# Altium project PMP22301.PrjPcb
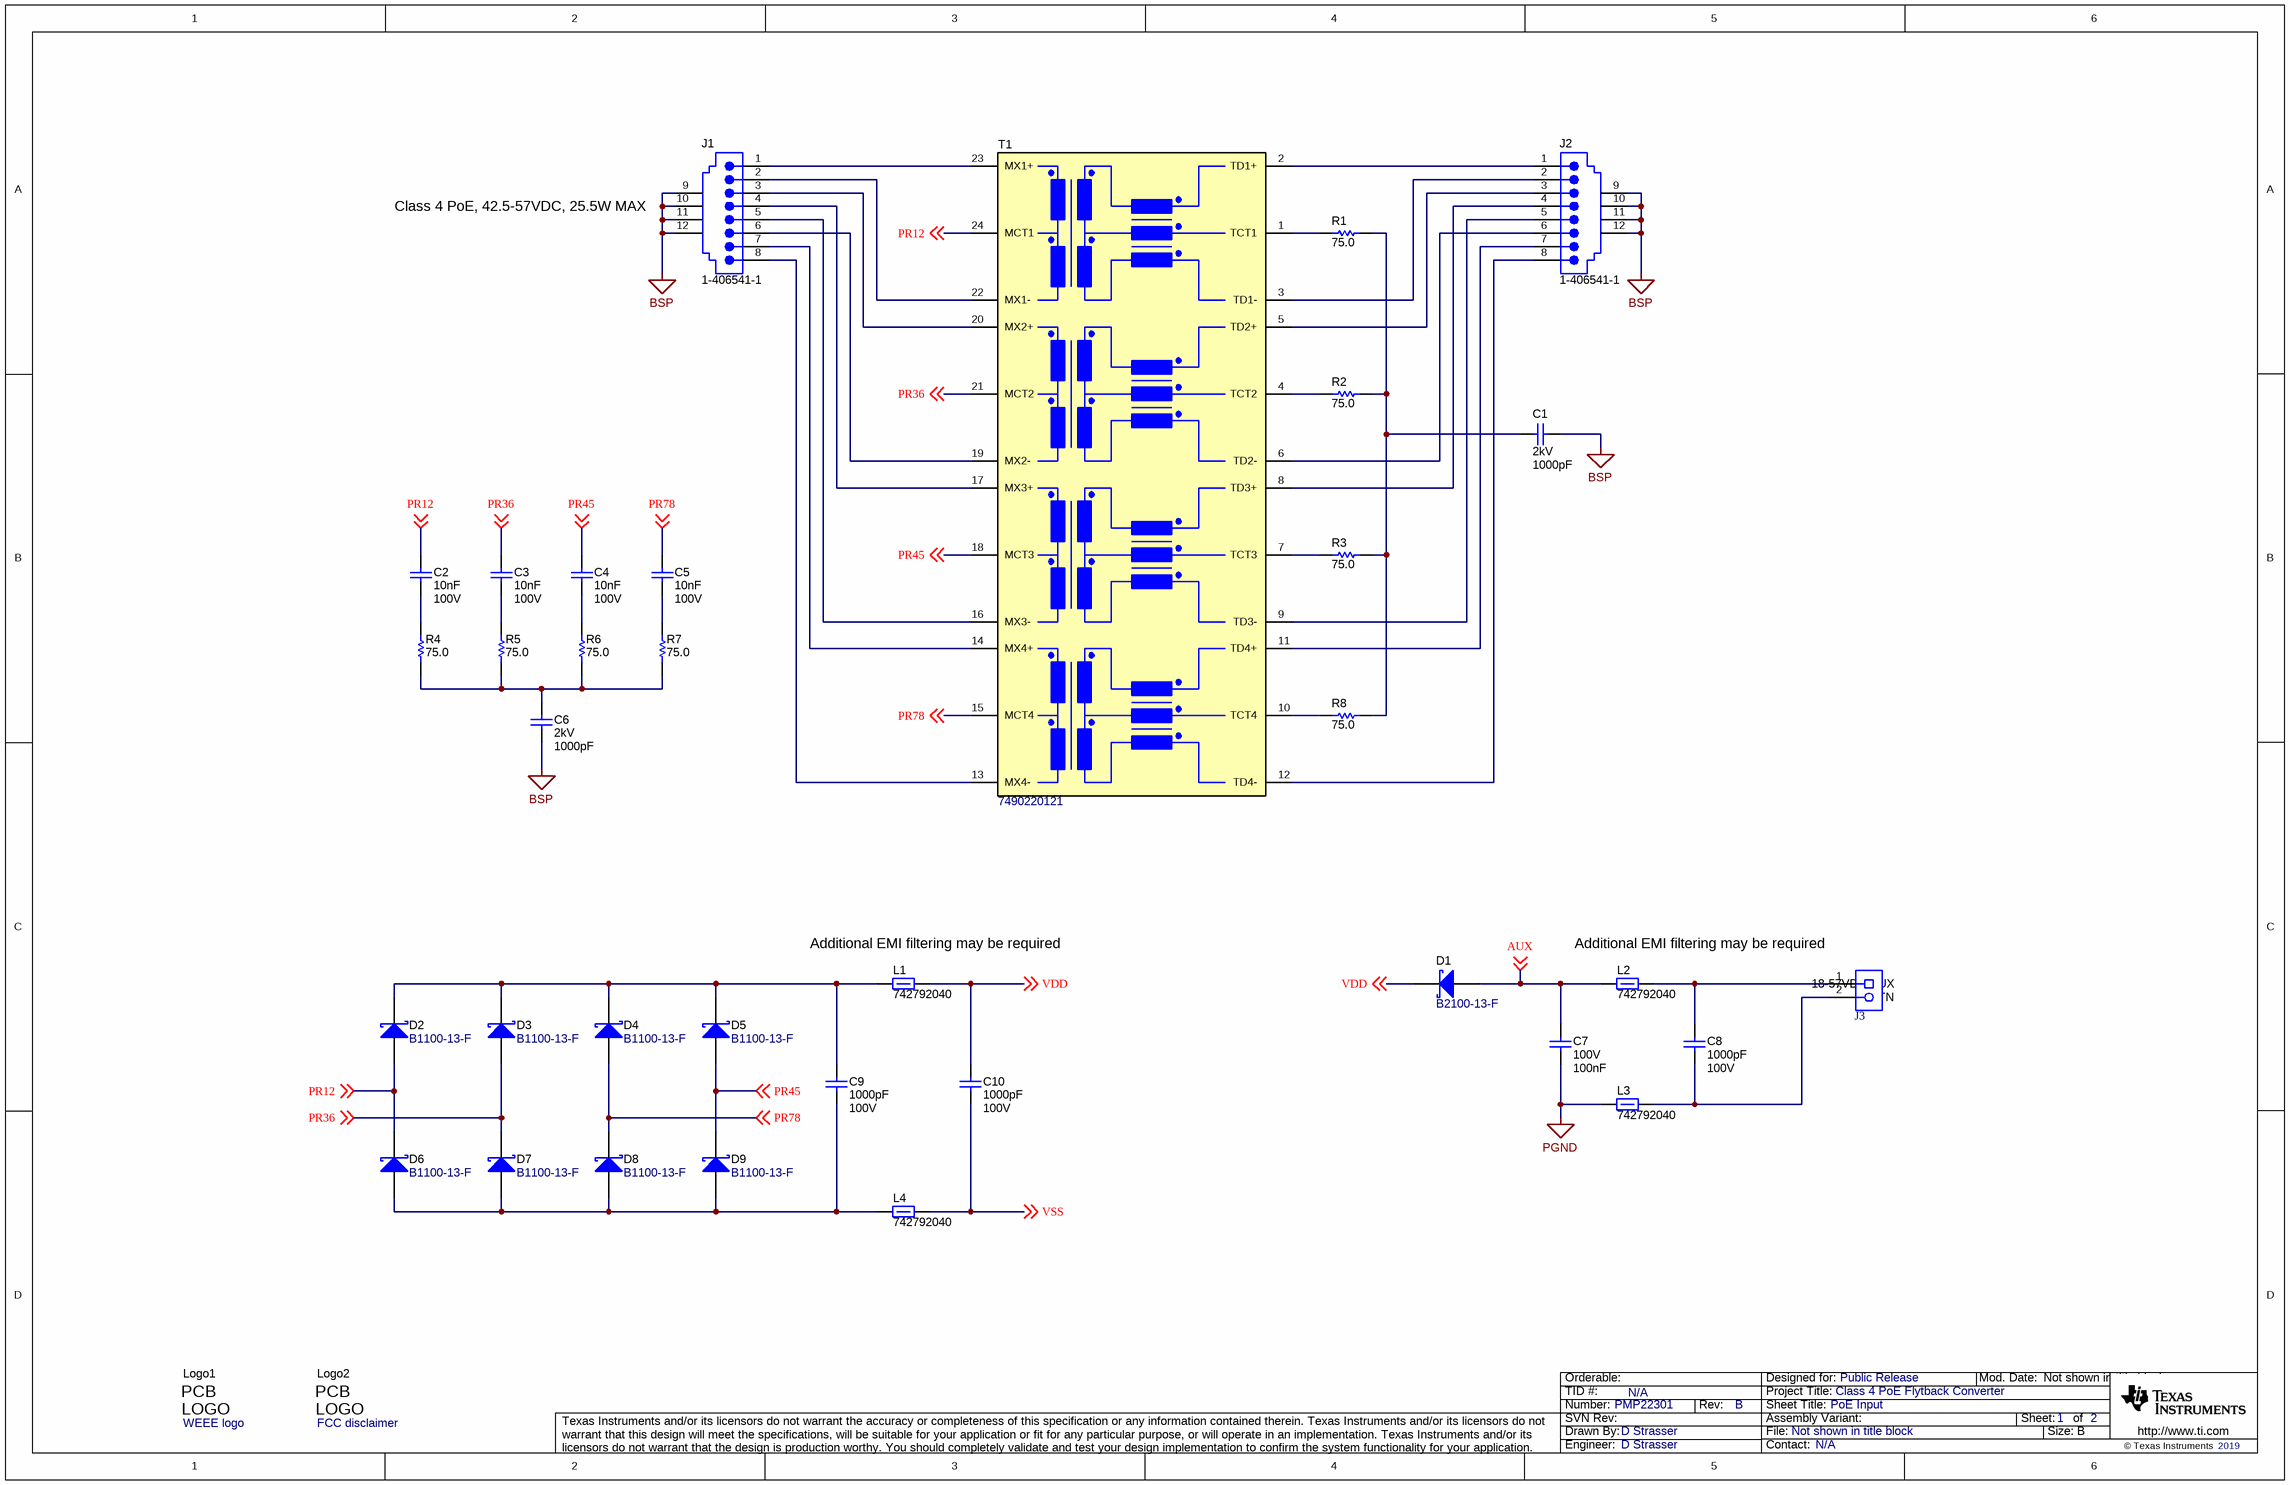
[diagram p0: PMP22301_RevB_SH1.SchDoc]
CopyrightYear: 2019; PCB_Layout: D Strasser; PCB_Rev: B; PRJ_Customer: Public Release; PRJ_Engineer: D Strasser; PRJ_Number: PMP22301; PRJ_Title: Class 4 PoE Flytback Converter; SCH_Rev: B; TechSupport: N/A; TID: N/A
2 sheets, 104 parts. Net scope: global (net labels, ports and power ports of the same name join across sheets).
Board file: PMP22301_RevB_PCB.PcbDoc
Sheets:
  PMP22301_RevB_SH1.SchDoc
  PMP22301_RevB_SH2.SchDoc

## Sheet PMP22301_RevB_SH1.SchDoc: PoE Input
size 431 x 279 mm; Date: Not shown in title block; ApprovedBy: Not shown in title block; CheckedBy: Not shown in title block; Author: Not shown in title block; CompanyName: Not shown in title block; DrawnBy: D Strasser; Engineer: Not shown in title block; Organization: Not shown in title block; Address1: Not shown in title block; Address2: Not shown in title block; Address3: Not shown in title block; Address4: Not shown in title block; DocumentNumber: 1; Revision: Use project parameter SCH_Rev; SheetNumber: 1; SheetTotal: 2; PageSetup: Record=PageOptions¦CenterHorizontal=True¦CenterVertical=True¦PrintScale=1.00¦XCorrection=1.00¦YCorrection=1.00¦PrintKind=0¦BorderSize=5000000¦LeftOffset=0¦BottomOffset=0¦Orientation=2¦PaperLength=1000¦PaperWidth=1000¦Scale=100¦PaperSource=15¦PrintQuality=600¦MediaType=1¦DitherType=10¦PaperKind=Letter¦PrintScaleMode=1

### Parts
C1  VDC_V: 2kV  ValueDisplayed: 1000pF  [1812]  (hidden comment: GR443QR73D102KW01L)
C2  Cap_F: 10nF  VDC_V: 100V  [0603L]  (hidden comment: 885012206114)
C3  Cap_F: 10nF  VDC_V: 100V  [0603L]  (hidden comment: 885012206114)
C4  Cap_F: 10nF  VDC_V: 100V  [0603L]  (hidden comment: 885012206114)
C5  Cap_F: 10nF  VDC_V: 100V  [0603L]  (hidden comment: 885012206114)
C6  VDC_V: 2kV  ValueDisplayed: 1000pF  [1812]  (hidden comment: GR443QR73D102KW01L)
C7  VDC_V: 100V  Cap_F: 100nF  [0805_HV]  (hidden comment: 885012207128)
C8  ValueDisplayed: 1000pF  Value2: 100V  [0603L]  (hidden comment: Capacitor)
C9  ValueDisplayed: 1000pF  Value2: 100V  [0603L]  (hidden comment: Capacitor)
C10  ValueDisplayed: 1000pF  Value2: 100V  [0603L]  (hidden comment: Capacitor)
D1  B2100-13-F  [SMB]
D2  B1100-13-F  [SMA]
D3  B1100-13-F  [SMA]
D4  B1100-13-F  [SMA]
D5  B1100-13-F  [SMA]
D6  B1100-13-F  [SMA]
D7  B1100-13-F  [SMA]
D8  B1100-13-F  [SMA]
D9  B1100-13-F  [SMA]
J1  1-406541-1  [TEC_1-406541-1]
J2  1-406541-1  [TEC_1-406541-1]
J3  691214110002  [Wurth_691214110002]  (value not drawn)
L1  742792040  [0805_HV]
L2  742792040  [0805_HV]
L3  742792040  [0805_HV]
L4  742792040  [0805_HV]
Logo1  WEEE logo  [WEEE_Minimum]  (no BOM)
Logo2  FCC disclaimer  [FCC_disclaimer]  (no BOM)
R1  ValueDisplayed: 75.0  [0603L]  (hidden comment: Resistor)
R2  ValueDisplayed: 75.0  [0603L]  (hidden comment: Resistor)
R3  ValueDisplayed: 75.0  [0603L]  (hidden comment: Resistor)
R4  ValueDisplayed: 75.0  [0603L]  (hidden comment: Resistor)
R5  ValueDisplayed: 75.0  [0603L]  (hidden comment: Resistor)
R6  ValueDisplayed: 75.0  [0603L]  (hidden comment: Resistor)
R7  ValueDisplayed: 75.0  [0603L]  (hidden comment: Resistor)
R8  ValueDisplayed: 75.0  [0603L]  (hidden comment: Resistor)
T1  7490220121  [Wurth_7490220121]

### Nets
BSP: C1.1 C6.2 J1.9 J1.10 J1.11 J1.12 J2.9 J2.10 J2.11 J2.12
PGND: C7.1 L3.1
AUX: C7.2 D1.2(A) L2.1 ; off-sheet AUX
PR12: C2.2 D2.2(A) D6.1(K) T1.24(MCT1) ; off-sheet PR12
PR36: C3.2 D3.2(A) D7.1(K) T1.21(MCT2) ; off-sheet PR36
PR45: C4.2 D5.2(A) D9.1(K) T1.18(MCT3) ; off-sheet PR45
PR78: C5.2 D4.2(A) D8.1(K) T1.15(MCT4) ; off-sheet PR78
VDD: C10.1 D1.1(K) L1.2 ; off-sheet VDD
VSS: C10.2 L4.2 ; off-sheet VSS
NetC1_2: C1.2 R1.2 R2.2 R3.2 R8.1
NetC2_1: C2.1 R4.2
NetC3_1: C3.1 R5.2
NetC4_1: C4.1 R6.2
NetC5_1: C5.1 R7.2
NetC6_1: C6.1 R4.1 R5.1 R6.1 R7.1
NetC8_1: C8.1 J3.1 L2.2
NetC8_2: C8.2 J3.2 L3.2
NetC9_1: C9.1 D2.1(K) D3.1(K) D4.1(K) D5.1(K) L1.1
NetC9_2: C9.2 D6.2(A) D7.2(A) D8.2(A) D9.2(A) L4.1
NetJ1_1: J1.1 T1.23(MX1+)
NetJ1_2: J1.2 T1.22(MX1-)
NetJ1_3: J1.3 T1.20(MX2+)
NetJ1_4: J1.4 T1.17(MX3+)
NetJ1_5: J1.5 T1.16(MX3-)
NetJ1_6: J1.6 T1.19(MX2-)
NetJ1_7: J1.7 T1.14(MX4+)
NetJ1_8: J1.8 T1.13(MX4-)
NetJ2_1: J2.1 T1.2(TD1+)
NetJ2_2: J2.2 T1.3(TD1-)
NetJ2_3: J2.3 T1.5(TD2+)
NetJ2_4: J2.4 T1.8(TD3+)
NetJ2_5: J2.5 T1.9(TD3-)
NetJ2_6: J2.6 T1.6(TD2-)
NetJ2_7: J2.7 T1.11(TD4+)
NetJ2_8: J2.8 T1.12(TD4-)
NetR1_1: R1.1 T1.1(TCT1)
NetR2_1: R2.1 T1.4(TCT2)
NetR3_1: R3.1 T1.7(TCT3)
NetR8_2: R8.2 T1.10(TCT4)

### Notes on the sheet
- Class 4 PoE, 42.5-57VDC, 25.5W MAX
- (near L1) Additional EMI filtering may be required
- Additional EMI filtering may be required
- (near J3) RTN
- (near J3) 18-57VDC AUX

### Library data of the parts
C1 C6 = CMP-0009438-2: CAP, CERM, 1000 pF, 2000 V, +/- 10%, X7R, 1812; Manufacturer: MuRata; TaMin_C: -55°C; Polarized: N; SizeAreaWB_mm2: 23.1; Value1: Unknown; U/M: EA; Value: 1000pF; TaMax_C: 125°C; SizeZ_mm: 1.35; SizeX_mm: 4.5; SizeY_mm: 3.2; Value2: 2000V; SizeArea_mm2: 14.4; Cap_F: 1nF; AEC Category: Q200
C2-C5 = CMP-0079993-1: CAP, CERM, 0.01 µF, 100 V,+/- 10%, X7R, 0603; Manufacturer: Wurth Elektronik; TaMin_C: -55°C; Polarized: N; SizeAreaWB_mm2: 4.68; U/M: EA; Value: 0.01uF; TaMax_C: 105°C; SizeZ_mm: 1; SizeX_mm: 1.6; SizeY_mm: 0.8; Cap_Case: 0603; SizeArea_mm2: 1.28; AEC Category: Q200; ValueDisplayed: 0.01µF
C7 = CMP-0750058-1: CAP, CERM, 0.1 µF, 100 V,+/- 10%, X7R, 0805; Manufacturer: Wurth Elektronik; TaMin_C: -55°C; AEC Category: Q200; U/M: EA; SizeY_mm: 1.25; Polarized: N; Value: 0.1uF; SizeX_mm: 2; TaMax_C: 125°C; ValueDisplayed: 0.1µF; SizeArea_mm2: 2.5; Cap_Case: 0805; SizeZ_mm: 1.45; SizeAreaWB_mm2: 6.75
C8-C10 = CMP-0007053-4: CAP, CERM, 1000 pF, 100 V, +/- 10%, X7R, 0603; PartNumber: C1608X7R2A102K080AA; Manufacturer: TDK; Polarized: N; Value: 1000pF; U/M: EA; Cap_F: 1nF; Value1: Unknown; TaMin_C: -55°C; TaMax_C: 125°C; Cap_Case: 0603; SizeArea_mm2: 1.28; SizeAreaWB_mm2: 4.68; SizeX_mm: 1.6; SizeY_mm: 0.8; SizeZ_mm: 1; AEC Category: Q200
D1 = CMP-0028397-2: Diode, Schottky, 100 V, 2 A, SMB; Manufacturer: Diodes Inc.; Value2: 0.79V; Value1: 2A; SizeArea_mm2: 21.336; Value: 100V; Green_REACh: Passed; Green_Lifecycle: Active; Vf_V: 790mV; SizeY_mm: 3.81; AEC Category: Q101; SizeZ_mm: 2.6; TJmax_C: 150°C; RJC_CperW: 15; SizeAreaWB_mm2: 44.156; SizeX_mm: 5.6
D2-D9 = CMP-0028371-2: Diode, Schottky, 100 V, 1 A, SMA; Manufacturer: Diodes Inc.; Io_A: 1A; SizeZ_mm: 2.87; Green_REACh: Passed; TJmax_C: 150°C; Value: 100V; SizeAreaWB_mm2: 37.3428; Vf_V: 790mV; RJC_CperW: 25; SizeX_mm: 5.59; AEC Category: Q101; SizeArea_mm2: 16.3228; SizeY_mm: 2.92; Value2: 0.79V; Green_Lifecycle: Active
J1 J2 = CMP-0054918-1: RJ45, No LED, tab up, R/A, TH; Manufacturer: TE Connectivity; CNHeader: FALSE; Green_Lifecycle: Active; Green_REACh: Passed; ContactFinish: Gold; CT: TRUE
J3 = CMP-0054825-2: Terminal Block, 3.5mm, 2x1, Tin, TH; Manufacturer: Wurth Elektronik; Pitch_mm: 3.5; CT: TRUE; CNHeader: FALSE; Voltage_V: 300V; Gender: Female; Cert_UL: Y; Row_Count: 1; Current_A: 10A
L1-L4 = CMP-0003084-1: Ferrite Bead, 600 ohm @ 100 MHz, 2 A, 0805; Manufacturer: Wurth Elektronik; Ztyp@1GHz_Ohm: 193.403; ZTyp@100MHz_Ohm: 600; SizeAreaWB_mm2: 6.75; DCR_ohm: 1.5d; Value1: 0.15 ohm; Value: 600 ohm; Imax_A: 2A; SizeZ_mm: 1.45; SizeX_mm: 2; SizeY_mm: 1.25; SizeArea_mm2: 2.5
Logo1 = CMP-0074769-1
Logo2 = CMP-0074847-1: FCC_disclaimer
R1-R8 = CMP-0022590-4: RES, 75.0, 1%, 0.1 W, AEC-Q200 Grade 0, 0603; PartNumber: CRCW060375R0FKEA; Manufacturer: Vishay-Dale; Value: 75.0; Res_ohm: 75; Value_Code: 75R0; Power_W: 100mW; Value2: 0.1W; VDC_V: 75V; TempCo: 100 ppm/C; SizeArea_mm2: 1.28; SizeX_mm: 1.6; SizeY_mm: 0.8; SizeZ_mm: 1; EIA_Code: E96; AEC Category: Q200; AEC Qualified: Y; AEC Grade: 0
T1 = CMP-0030595-1: Transformer, 350 uH, SMT; Manufacturer: Wurth Elektronik; Value: 350uH; Ind_H: 350µH; Lp: 350

## Sheet PMP22301_RevB_SH2.SchDoc: Flyback Converter
size 431 x 279 mm; Date: Not shown in title block; ApprovedBy: Not shown in title block; CheckedBy: Not shown in title block; Author: Not shown in title block; CompanyName: Not shown in title block; DrawnBy: D Strasser; Engineer: Not shown in title block; Organization: Not shown in title block; Address1: Not shown in title block; Address2: Not shown in title block; Address3: Not shown in title block; Address4: Not shown in title block; DocumentNumber: 2; Revision: Use project parameter SCH_Rev; SheetNumber: 2; SheetTotal: 2; PageSetup: Record=PageOptions¦CenterHorizontal=True¦CenterVertical=True¦PrintScale=1.00¦XCorrection=1.00¦YCorrection=1.00¦PrintKind=0¦BorderSize=5000000¦LeftOffset=0¦BottomOffset=0¦Orientation=2¦PaperLength=1000¦PaperWidth=1000¦Scale=100¦PaperSource=15¦PrintQuality=600¦MediaType=1¦DitherType=10¦PaperKind=Letter¦PrintScaleMode=1
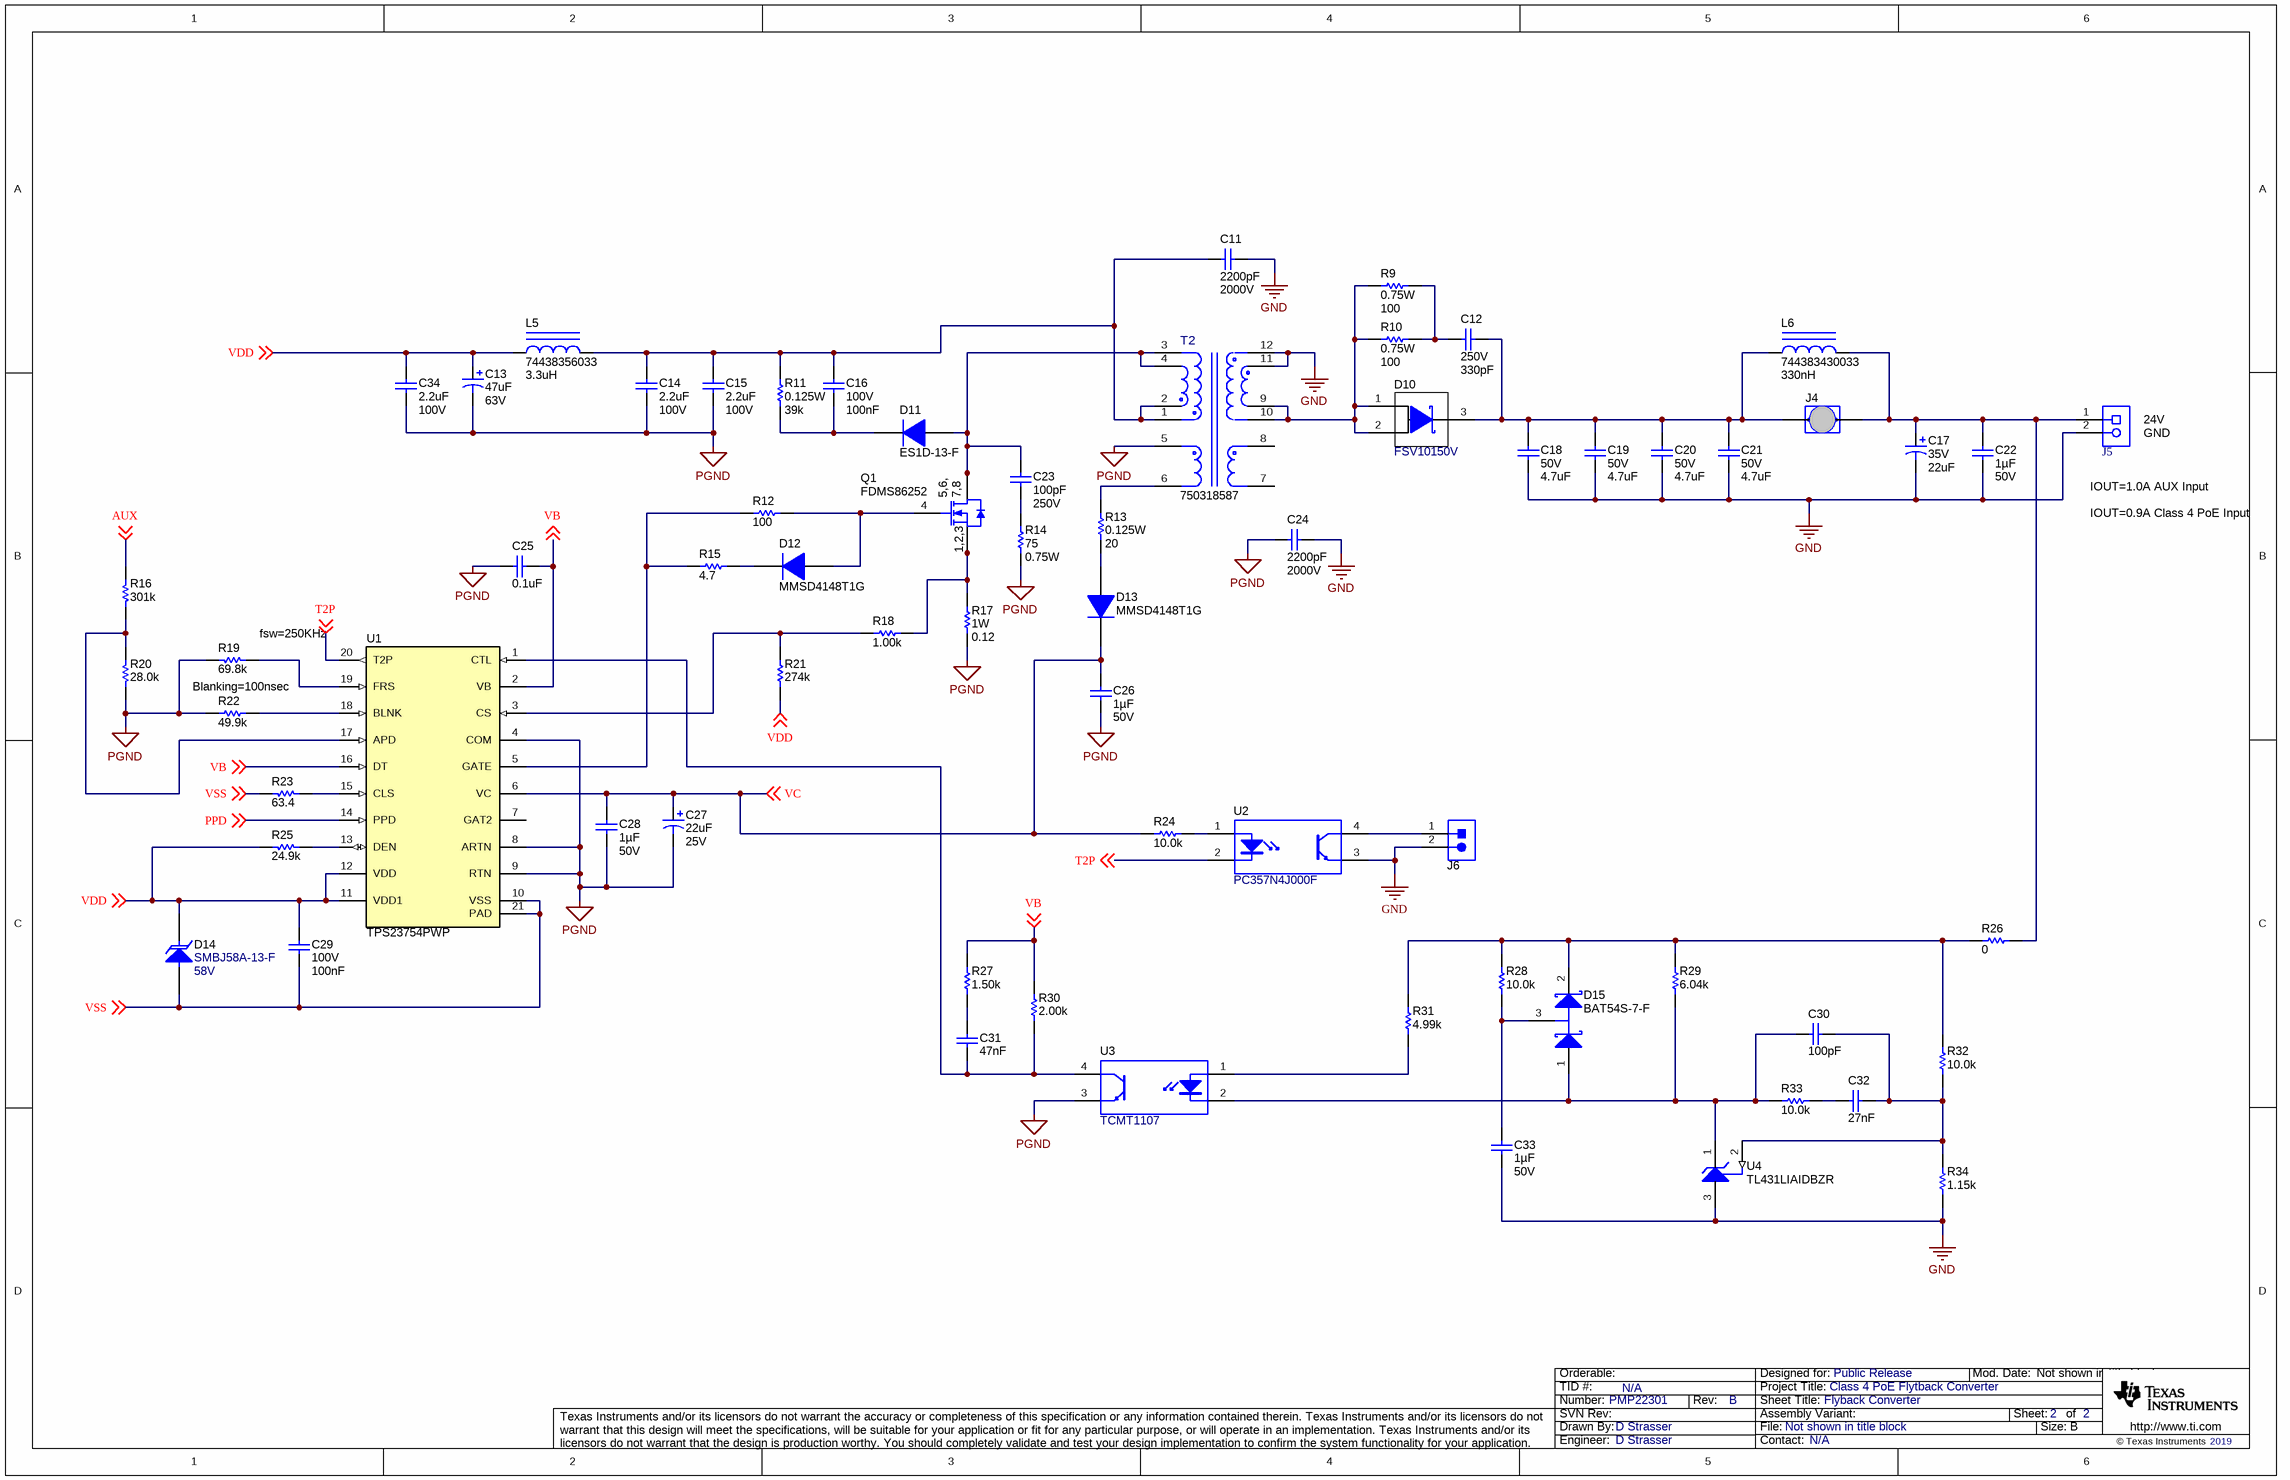
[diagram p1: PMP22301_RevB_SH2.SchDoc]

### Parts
C11  ValueDisplayed: 2200pF  Value2: 2000V  [1812_HV]  (hidden comment: Capacitor)
C12  VDC_V: 250V  ValueDisplayed: 330pF  [0805_HV]  (hidden comment: GRM21A5C2E331JW01D)
C13  ValueDisplayed: 47uF  Value2: 63V  [SM_RADIAL_F]  (hidden comment: Cap_Polarized)
C14  ValueDisplayed: 2.2uF  Value2: 100V  [1210_270L]  (hidden comment: Capacitor)
C15  ValueDisplayed: 2.2uF  Value2: 100V  [1210_270L]  (hidden comment: Capacitor)
C16  VDC_V: 100V  Cap_F: 100nF  [0805_HV]  (hidden comment: 885012207128)
C17  VDC_V: 35V  ValueDisplayed: 22uF  [CAPSMT_62_F61]  (hidden comment: 35SVPF22M)
C18  VDC_V: 50V  ValueDisplayed: 4.7uF  [1210_270]  (hidden comment: GRM32ER71H475KA88L)
C19  VDC_V: 50V  ValueDisplayed: 4.7uF  [1210_270]  (hidden comment: GRM32ER71H475KA88L)
C20  VDC_V: 50V  ValueDisplayed: 4.7uF  [1210_270]  (hidden comment: GRM32ER71H475KA88L)
C21  VDC_V: 50V  ValueDisplayed: 4.7uF  [1210_270]  (hidden comment: GRM32ER71H475KA88L)
C22  Cap_F: 1µF  VDC_V: 50V  [0805L]  (hidden comment: 885012207103)
C23  ValueDisplayed: 100pF  Value2: 250V  [0805_HV]  (hidden comment: Capacitor)
C24  ValueDisplayed: 2200pF  Value2: 2000V  [1812_HV]  (hidden comment: Capacitor)
C25  ValueDisplayed: 0.1uF  [0603L]  (hidden comment: Capacitor)
C26  Cap_F: 1µF  VDC_V: 50V  [0805L]  (hidden comment: 885012207103)
C27  ValueDisplayed: 22uF  Value2: 25V  [SM_RADIAL_C]  (hidden comment: Cap_Polarized)
C28  Cap_F: 1µF  VDC_V: 50V  [0805L]  (hidden comment: 885012207103)
C29  VDC_V: 100V  Cap_F: 100nF  [0805_HV]  (hidden comment: 885012207128)
C30  ValueDisplayed: 100pF  [0603L]  (hidden comment: Capacitor)
C31  Cap_F: 47nF  [0603L]  (hidden comment: GRM188R71E473KA01D)
C32  Cap_F: 27nF  [0603L]  (hidden comment: GRM188R71E273KA01D)
C33  Cap_F: 1µF  VDC_V: 50V  [0805L]  (hidden comment: 885012207103)
C34  ValueDisplayed: 2.2uF  Value2: 100V  [1210_270L]  (hidden comment: Capacitor)
D10  FSV10150V  [TO-277A]
D11  ES1D-13-F  [SMA]
D12  MMSD4148T1G  [SOD-123]
D13  MMSD4148T1G  [SOD-123]
D14  SMBJ58A-13-F  value 58V  [SMB]
D15  BAT54S-7-F  [SOT-23L]
J4  999-11-110-10-000000  [Mill-Max_999-11-110-10-000000]  (value not drawn)
J5  691214110002  [Wurth_691214110002]  (value not drawn)
J6  61300211121  [WURTH_61300211121]  (value not drawn)
L5  PartNumber: 74438356033  ValueDisplayed: 3.3uH  [WE-MAPI_4020]  (hidden comment: 74438356022)
L6  ValueDisplayed: 330nH  [WE-MAPI_2010]  (hidden comment: 744383430033)
Q1  FDMS86252  [TRANS_Fairchild_PQFN08A]
R9  Value2: 0.75W  ValueDisplayed: 100  [2010]  (hidden comment: CRCW2010100RJNEF)
R10  Value2: 0.75W  ValueDisplayed: 100  [2010]  (hidden comment: CRCW2010100RJNEF)
R11  Value2: 0.125W  ValueDisplayed: 39k  [0805_HV]  (hidden comment: CRCW080539K0JNEA)
R12  ValueDisplayed: 100  [0603L]  (hidden comment: CRCW0603100RJNEA)
R13  Value2: 0.125W  ValueDisplayed: 20  [0805L]  (hidden comment: CRCW080520R0JNEA)
R14  ValueDisplayed: 75  Value2: 0.75W  [2010L]  (hidden comment: Resistor)
R15  ValueDisplayed: 4.7  [0603L]  (hidden comment: Resistor)
R16  ValueDisplayed: 301k  [0603L]  (hidden comment: CRCW0603301KFKEA)
R17  Value2: 1W  ValueDisplayed: 0.12  [2512]  (hidden comment: ERJ-L1WKF10CU)
R18  ValueDisplayed: 1.00k  [0603L]  (hidden comment: CRCW06031K00FKEA)
R19  ValueDisplayed: 69.8k  [0603L]  (hidden comment: Resistor)
R20  ValueDisplayed: 28.0k  [0603L]  (hidden comment: CRCW060328K0FKEA)
R21  ValueDisplayed: 274k  [0603L]  (hidden comment: CRCW0603274KFKEA)
R22  ValueDisplayed: 49.9k  [0603L]  (hidden comment: CRCW060349K9FKEA)
R23  ValueDisplayed: 63.4  [0805L]  (hidden comment: Resistor)
R24  ValueDisplayed: 10.0k  [0603L]  (hidden comment: CRCW060310K0FKEA)
R25  ValueDisplayed: 24.9k  [0603L]  (hidden comment: Resistor)
R26  ValueDisplayed: 0  [0603L]  (hidden comment: Resistor)
R27  ValueDisplayed: 1.50k  [0603L]  (hidden comment: CRCW06031K50FKEA)
R28  ValueDisplayed: 10.0k  [0603L]  (hidden comment: Resistor)
R29  ValueDisplayed: 6.04k  [0603L]  (hidden comment: CRCW06036K04FKEA)
R30  ValueDisplayed: 2.00k  [0603L]  (hidden comment: Resistor)
R31  ValueDisplayed: 4.99k  [0603L]  (hidden comment: CRCW06034K99FKEA)
R32  ValueDisplayed: 10.0k  [0603L]  (hidden comment: CRCW060310K0FKEA)
R33  ValueDisplayed: 10.0k  [0603L]  (hidden comment: CRCW060310K0FKEA)
R34  ValueDisplayed: 1.15k  [0603L]  (hidden comment: CRCW06031K15FKEA)
T2  PartNumber: 750318587  [FP-PA6399-AL_SMT_TRANSFORMER_20MM57_20MM57-MFG]  (hidden comment: PA6399-AL)
U1  TPS23754PWP  [PWP0020D_M]
U2  PC357N4J000F  [BESOP-4]
U3  TCMT1107  [SOP-4]
U4  TL431LIAIDBZR  [DBZ0003A_L]

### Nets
GND: C11.1 C17.2(-) C18.1 C19.1 C20.1 C21.1 C22.2 C24.1 C33.2 J5.2 J6.2 R34.2 T2.11 T2.12 U2.3(E) U4.3(ANODE)
PGND: C13.2(-) C14.2 C15.2 C24.2 C25.1 C26.2 C27.2(-) C28.2 C34.2 R14.1 R17.2 R19.2 R20.2 R22.1 T2.5 U1.4(COM) U1.8(ARTN) U1.9(RTN) U3.3(E)
AUX: R16.2 ; off-sheet AUX
PPD: U1.14(PPD) ; off-sheet PPD
T2P: U1.20(T2P) U2.2(K) ; off-sheet T2P
VB: C25.2 R27.1 R30.2 U1.2(VB) U1.16(DT) ; off-sheet VB
VC: C26.1 C27.1(+) C28.1 D13.1(K) R24.2 U1.6(VC) ; off-sheet VC
VDD: C13.1(+) C29.2 C34.1 D14.1(K) L5.1 R21.2 R25.2 U1.11(VDD1) U1.12(VDD) ; off-sheet VDD
VSS: C29.1 D14.2(A) R23.2 U1.10(VSS) U1.21(PAD) ; off-sheet VSS
NetC11_2: C11.2 C14.1 C15.1 C16.2 L5.2 R11.2 T2.1 T2.2
NetC12_1: C12.1 C18.2 C19.2 C20.2 C21.2 D10.3(K) J4.1 L6.1
NetC12_2: C12.2 R9.2 R10.2
NetC16_1: C16.1 D11.1(K) R11.1
NetC17_1: C17.1(+) C22.1 J4.2 J5.1 L6.2 R26.2
NetC23_1: C23.1 D11.2(A) Q1.5(D) Q1.6(D) Q1.7(D) Q1.8(D) T2.3 T2.4
NetC23_2: C23.2 R14.2
NetC30_1: C30.1 C32.1 R32.1 R34.1 U4.2(REF)
NetC30_2: C30.2 D15.1(A) R29.2 R33.2 U3.2(K) U4.1(CATHODE)
NetC31_1: C31.1 R30.1 U1.1(CTL) U3.4(C)
NetC31_2: C31.2 R27.2
NetC32_2: C32.2 R33.1
NetC33_1: C33.1 D15.3(C) R28.1
NetD10_1: D10.1(A) D10.2(A) R9.1 R10.1 T2.9 T2.10
NetD12_1: D12.1(K) R15.2
NetD12_2: D12.2(A) Q1.4(G) R12.2
NetD13_2: D13.2(A) R13.2
NetD15_2: D15.2(K) R26.1 R28.2 R29.1 R31.2 R32.2
NetJ6_1: J6.1 U2.4(C)
NetQ1_1: Q1.1(S) Q1.2(S) Q1.3(S) R17.1 R18.2
NetR12_1: R12.1 R15.1 U1.5(GATE)
NetR13_1: R13.1 T2.6
NetR16_1: R16.1 R20.1 U1.17(APD)
NetR18_1: R18.1 R21.1 U1.3(CS)
NetR19_1: R19.1 U1.19(FRS)
NetR22_2: R22.2 U1.18(BLNK)
NetR23_1: R23.1 U1.15(CLS)
NetR24_1: R24.1 U2.1(A)
NetR25_1: R25.1 U1.13(DEN)
NetR31_1: R31.1 U3.1(A)

Not connected (* = marked no-connect by the designer): T2 7 8; U1 7(GAT2)

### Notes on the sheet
- (near J5) GND
- (near J5) 24V
- (near J5) IOUT=1.0A AUX Input
- IOUT=0.9A Class 4 PoE Input
- (near R19) fsw=250KHz
- Blanking=100nsec

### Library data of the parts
C11 C24 = CMP-0009358-2: CAP, CERM, 2200 pF, 2000 V, +/- 10%, X7R, 1812; PartNumber: C4532X7R3D222K130KA; Manufacturer: TDK; Polarized: N; Value: 2200pF; U/M: EA; Cap_F: 2.2nF; Value1: Unknown; VDC_V: 2kV; TaMin_C: -55°C; TaMax_C: 125°C; Cap_Case: 1812; SizeArea_mm2: 14.4; SizeAreaWB_mm2: 23.1; SizeX_mm: 4.5; SizeY_mm: 3.2; SizeZ_mm: 1.35; AEC Category: Q200
C12 = CMP-0081666-1: CAP, CERM, 330 pF, 250 V,+/- 5%, C0G/NP0, 0805; Manufacturer: MuRata; SizeAreaWB_mm2: 6.75; SizeArea_mm2: 2.5; AEC Qualified: N; AEC Category: Q200; Value: 330pF; TaMax_C: 125°C; SizeZ_mm: 1.45; TaMin_C: -55°C; SizeY_mm: 1.25; U/M: EA; SizeX_mm: 2; Cap_Case: 0805
C13 = CMP-0011192-2: CAP, AL, 47 uF, 63 V, +/- 20%, 0.65 ohm, AEC-Q200 Grade 2, SMD; PartNumber: EEE-FK1J470P; Manufacturer: Panasonic; Polarized: Y; CompType: Capacitor; Value: 47uF; U/M: EA; Cap_F: 47µF; ESR_ohm: 6.5d; IRMS_A: 2.5dA; TaMin_C: -55°C; TaMax_C: 105°C; Cap_Case: F; AEC Category: Q200; AEC Grade: 2; SizeArea_mm2: 83; SizeAreaWB_mm2: 123.6; SizeX_mm: 10; SizeY_mm: 8.3; SizeZ_mm: 10.2
C14 C15 C34 = CMP-0009232-2: CAP, CERM, 2.2 uF, 100 V, +/- 10%, X7R, 1210; PartNumber: GRM32ER72A225KA35L; Manufacturer: MuRata; Polarized: N; Value: 2.2uF; U/M: EA; Cap_F: 2.2µF; ESR_ohm: 7m; Value1: 0.007 ohm; IRMS_A: 4.4A; TaMin_C: -55°C; TaMax_C: 125°C; Cap_Case: 1210; SizeArea_mm2: 8; SizeAreaWB_mm2: 14.7; SizeX_mm: 3.2; SizeY_mm: 2.5; SizeZ_mm: 2.7; AEC Category: Q200
C16 C29 = CMP-0750058-1: as C7 on sheet PMP22301_RevB_SH1
C17 = CMP-0012134-3: CAP, Aluminum Polymer, 22 uF, 35 V, +/- 20%, 0.035 ohm, F61 SMD; Manufacturer: Panasonic; TaMin_C: -55°C; ESR_ohm: 0.035; Polarized: Y; SizeAreaWB_mm2: 73.96; Value: 22uF; TaMax_C: 105°C; SizeZ_mm: 5.8; SizeX_mm: 6.6; SizeArea_mm2: 43.56; CompType: Capacitor; Cap_F: 22µF; IRMS_A: 2.6A; AEC Category: Q200
C18-C21 = CMP-0009228-2: CAP, CERM, 4.7 uF, 50 V, +/- 10%, X7R, 1210; Manufacturer: MuRata; TaMin_C: -55°C; ESR_ohm: 2m; Polarized: N; SizeAreaWB_mm2: 14.7; Value1: 0.002 ohm; U/M: EA; Value: 4.7uF; TaMax_C: 125°C; SizeZ_mm: 2.7; SizeX_mm: 3.2; SizeY_mm: 2.5; Cap_Case: 1210; SizeArea_mm2: 8; Cap_F: 4.7µF; AEC Category: Q200
C22 C26 C28 C33 = CMP-0007696-2: CAP, CERM, 1 uF, 50 V, +/- 10%, X7R, 0805; Manufacturer: Wurth Elektronik; TaMin_C: -55°C; Polarized: N; SizeAreaWB_mm2: 6.75; Value1: Unknown; U/M: EA; Value: 1uF; TaMax_C: 125°C; SizeZ_mm: 1.45; SizeX_mm: 2; SizeY_mm: 1.25; Cap_Case: 0805; SizeArea_mm2: 2.5; AEC Category: Q200
C23 = CMP-0008236-2: CAP, CERM, 100 pF, 250 V, +/- 5%, C0G/NP0, 0805; PartNumber: GRM21A5C2E101JW01D; Manufacturer: MuRata; Polarized: N; Value: 100pF; U/M: EA; Value1: Unknown; TaMin_C: -55°C; TaMax_C: 125°C; Cap_Case: 0805; SizeArea_mm2: 2.5; SizeAreaWB_mm2: 6.75; SizeX_mm: 2; SizeY_mm: 1.25; SizeZ_mm: 1.45; AEC Category: Q200
C25 = CMP-0007039-5: CAP, CERM, 0.1 uF, 25 V, +/- 10%, X7R, 0603; PartNumber: C1608X7R1E104K080AA; Manufacturer: TDK; Polarized: N; Value: 0.1uF; U/M: EA; Cap_F: 100nF; Value1: Unknown; VDC_V: 25V; TaMin_C: -55°C; TaMax_C: 125°C; Cap_Case: 0603; SizeArea_mm2: 1.28; SizeAreaWB_mm2: 4.68; SizeX_mm: 1.6; SizeY_mm: 0.8; SizeZ_mm: 1; AEC Category: Q200
C27 = CMP-0010713-1: CAP, AL, 22 uF, 25 V, +/- 20%, 0.7 ohm, AEC-Q200 Grade 2, SMD; PartNumber: EEE-FK1E220R; Manufacturer: Panasonic; Polarized: Y; CompType: Capacitor; Value: 22uF; U/M: EA; Cap_F: 22µF; Value1: 0.7 ohm; ESR_ohm: 7d; IRMS_A: 1.6dA; TaMin_C: -55°C; TaMax_C: 105°C; Cap_Case: C; SizeAreaWB_mm2: 62.05; SizeArea_mm2: 34.45; SizeX_mm: 6.5; SizeY_mm: 5.3; SizeZ_mm: 5.4; AEC Category: Q200; AEC Grade: 2
C30 = CMP-0007171-4: CAP, CERM, 100 pF, 50 V, +/- 5%, C0G/NP0, 0603; PartNumber: GRM1885C1H101JA01D; Manufacturer: MuRata; Polarized: N; Value: 100pF; U/M: EA; Value1: Unknown; VDC_V: 50V; TaMin_C: -55°C; TaMax_C: 125°C; Cap_Case: 0603; SizeArea_mm2: 1.28; SizeAreaWB_mm2: 4.68; SizeX_mm: 1.6; SizeY_mm: 0.8; SizeZ_mm: 1; AEC Category: Q200
C31 = CMP-0007423-4: CAP, CERM, 0.047 uF, 25 V, +/- 10%, X7R, 0603; Manufacturer: MuRata; TaMin_C: -55°C; Polarized: N; SizeAreaWB_mm2: 4.68; Value1: Unknown; U/M: EA; TaMax_C: 125°C; SizeZ_mm: 1; SizeX_mm: 1.6; SizeY_mm: 0.8; Cap_Case: 0603; Value2: 25V; SizeArea_mm2: 1.28; AEC Category: Q200
C32 = CMP-0007417-5: CAP, CERM, 0.027 uF, 25 V, +/- 10%, X7R, 0603; Manufacturer: MuRata; TaMin_C: -55°C; Polarized: N; SizeAreaWB_mm2: 4.68; Value1: Unknown; U/M: EA; TaMax_C: 125°C; SizeZ_mm: 1; SizeX_mm: 1.6; SizeY_mm: 0.8; Cap_Case: 0603; Value2: 25V; SizeArea_mm2: 1.28; AEC Category: Q200
D10 = CMP-0028890-2: Diode, Schottky, 150 V, 10 A, AEC-Q101, TO-277A; Manufacturer: Fairchild Semiconductor; Value2: 0.84V; SizeAreaWB_mm2: 57.375; Value1: 10A; SizeArea_mm2: 30.875; SizeY_mm: 4.75; Green_REACh: Incomplete; SizeX_mm: 6.5; AEC Qualified: Y; SizeZ_mm: 1.2; AEC Category: Q101; TJmax_C: 150°C; Vf_V: 840mV; Value: 150V; Green_Lifecycle: Not Set
D11 = CMP-0029024-2: Diode, Ultrafast, 200 V, 1 A, SMA; Manufacturer: Diodes Inc.; Vf_V: 920mV; Value: 200V; Value1: 1A; Value2: 0.92V; TJmax_C: 150°C; RJC_CperW: 25; SizeAreaWB_mm2: 37.3428; SizeArea_mm2: 16.3228; SizeX_mm: 5.59; SizeY_mm: 2.92; SizeZ_mm: 2.87; AEC Category: Q101; Green_Lifecycle: Active; Green_REACh: Passed
D12 D13 = CMP-0029032-2: Diode, Switching, 100 V, 0.2 A, SOD-123; Manufacturer: ON Semiconductor; Vf_V: 1V; Value: 100V; Value1: 0.2A; Io_A: 200mA; TJmax_C: 150°C; SizeAreaWB_mm2: 13.095; SizeArea_mm2: 6.545; SizeX_mm: 3.85; SizeY_mm: 1.7; SizeZ_mm: 1.35; AEC Category: Q101; Green_Lifecycle: Active; Green_REACh: Passed
D14 = CMP-0005583-3: Diode, TVS, Uni, 58 V, 93.6 Vc, SMB; Manufacturer: Diodes Inc.; Vbr_Max: 74.6V; AEC Category: Q101; Ppk: 600W; Vbr_Min: 64.4V; SizeX_mm: 5.6; SizeZ_mm: 2.6; SizeY_mm: 3.81; Ipp: 6.4A; Vc: 93.6V; SizeAreaWB_mm2: 44.156; SizeArea_mm2: 21.336
D15 = CMP-0028456-2: Diode, Schottky, 30 V, 0.2 A, SOT-23; Manufacturer: Diodes Inc.; Vf_V: 650mV; Value: 30V; Value1: 0.2A; Value2: 0.65V; Io_A: 200mA; TJmax_C: 125°C; SizeAreaWB_mm2: 14; SizeArea_mm2: 7.5; SizeX_mm: 2.5; SizeY_mm: 3; SizeZ_mm: 1.1; AEC Category: Q101; Green_Lifecycle: Active; Green_REACh: Passed
J4 = CMP-0055047-1: Shorting Jumper, 2.54mm, 2 Position, Gold, TH; Manufacturer: Mill-Max; CNHeader: FALSE; Gender: Male; Pitch_mm: 2.54; Cert_UL: Y
J5 = CMP-0054825-2: as J3 on sheet PMP22301_RevB_SH1
J6 = CMP-0054794-2: Header, 2.54 mm, 2x1, Gold, TH; Manufacturer: Wurth Elektronik; Shrouded: N; Gender: Male; Green_REACh: Passed; Pitch_mm: 2.54; Green_Lifecycle: Active; Row_Count: 1; Cert_UL: Y
L5 = CMP-0064169-1: Inductor, Shielded, 3.3 uH, 3.6 A, 0.0399 ohm, SMD; Manufacturer: Wurth Elektronik; Isat: 6.2A @ 20% inductance drop; Irms: 4.7A @ 40C rise; Green_Lifecycle: Active; SizeAreaWB_mm2: 26.01; DCR_ohm: 0.029; Green_REACh: Passed; Value1: 0.029 ohm; Value: 2.2uH; Imax_A: 4.7A; SizeZ_mm: 2.1; SizeX_mm: 4.1; SizeArea_mm2: 16.81; Ind_H: 2.2µH; AEC Qualified: N; AEC Category: Q200
L6 = CMP-0064158-1: Inductor, Shielded, 330 nH, 2.5 A, 0.053 ohm, SMD; Manufacturer: Wurth Elektronik; Isat: 5.9A @ 20% inductance drop; Irms: 2.5A @ 40C rise; SizeAreaWB_mm2: 7.8; DCR_ohm: 0.053; Value: 330nH; Imax_A: 2.5A; SizeZ_mm: 1; SizeX_mm: 2; SizeY_mm: 1.6; SizeArea_mm2: 3.2; AEC Qualified: N; AEC Category: Q200
Q1 = CMP-0001058-1: MOSFET, N-CH, 150 V, 4.6 A, PQFN08A; Manufacturer: Fairchild Semiconductor; Alternate Manufacturer: None; U/M: EA; ChType: N; Value: 150V; Value1: 0; Rdson45_ohm: 0.07; Value2: 11 nC; QgTyp_nC: 11; Vgs_V: 20V; IdsMax_A: 4.6A; SizeAreaWB_mm2: 56; SizeArea_mm2: 30; SizeX_mm: 5; SizeY_mm: 6; SizeZ_mm: 1.1; AEC Category: Q101
R9 R10 = CMP-0016046-3: RES, 100, 5%, 0.75 W, AEC-Q200 Grade 0, 2010; Manufacturer: Vishay-Dale; Power_W: 750mW; TempCo: 200 ppm/C; Value_Code: 100R; Value: 100; EIA_Code: E24; SizeX_mm: 5; SizeY_mm: 2.5; SizeZ_mm: 1.66; SizeArea_mm2: 12.5; AEC Qualified: Y; VDC_V: 400V; AEC Grade: 0; AEC Category: Q200
R11 = CMP-0020536-3: RES, 39 k, 5%, 0.125 W, AEC-Q200 Grade 0, 0805; Manufacturer: Vishay-Dale; Power_W: 125mW; TempCo: 200 ppm/C; Value_Code: 39k0; Value: 39k; EIA_Code: E24; SizeX_mm: 2; SizeY_mm: 1.25; SizeZ_mm: 1.45; SizeArea_mm2: 2.5; AEC Qualified: Y; VDC_V: 150V; AEC Category: Q200; AEC Grade: 0
R12 = CMP-0025700-4: RES, 100, 5%, 0.1 W, AEC-Q200 Grade 0, 0603; Manufacturer: Vishay-Dale; Power_W: 100mW; TempCo: 200 ppm/C; Value_Code: 100R; Value: 100; EIA_Code: E24; SizeX_mm: 1.6; SizeY_mm: 0.8; SizeZ_mm: 1; Value2: 0.1W; SizeArea_mm2: 1.28; AEC Qualified: Y; VDC_V: 75V; AEC Category: Q200; AEC Grade: 0
R13 = CMP-0020497-3: RES, 20, 5%, 0.125 W, AEC-Q200 Grade 0, 0805; Manufacturer: Vishay-Dale; Power_W: 125mW; TempCo: 200 ppm/C; Value_Code: 20R0; Value: 20; EIA_Code: E24; SizeX_mm: 2; SizeY_mm: 1.25; SizeZ_mm: 1.45; SizeArea_mm2: 2.5; AEC Qualified: Y; VDC_V: 150V; AEC Category: Q200; AEC Grade: 0
R14 = CMP-0016178-3: RES, 75, 5%, 0.75 W, AEC-Q200 Grade 0, 2010; PartNumber: CRCW201075R0JNEF; Manufacturer: Vishay-Dale; Value: 75; Value_Code: 75R0; Power_W: 750mW; VDC_V: 400V; TempCo: 200 ppm/C; SizeArea_mm2: 12.5; SizeX_mm: 5; SizeY_mm: 2.5; SizeZ_mm: 1.66; EIA_Code: E24; AEC Category: Q200; AEC Qualified: Y; AEC Grade: 0
R15 = CMP-0025821-4: RES, 4.7, 5%, 0.1 W, AEC-Q200 Grade 0, 0603; PartNumber: CRCW06034R70JNEA; Manufacturer: Vishay-Dale; Value: 4.7; Value_Code: 4R70; Power_W: 100mW; Value2: 0.1W; VDC_V: 75V; TempCo: 200 ppm/C; SizeArea_mm2: 1.28; SizeX_mm: 1.6; SizeY_mm: 0.8; SizeZ_mm: 1; EIA_Code: E24; AEC Category: Q200; AEC Qualified: Y; AEC Grade: 0
R16 = CMP-0022320-4: RES, 301 k, 1%, 0.1 W, AEC-Q200 Grade 0, 0603; Manufacturer: Vishay-Dale; Power_W: 100mW; TempCo: 100 ppm/C; Value: 301k; EIA_Code: E96; SizeX_mm: 1.6; SizeY_mm: 0.8; SizeZ_mm: 1; Value2: 0.1W; SizeArea_mm2: 1.28; AEC Qualified: Y; VDC_V: 75V; AEC Category: Q200; AEC Grade: 0
R17 = CMP-0015806-2: RES, 0.12, 1%, 1 W, 2512; Manufacturer: Panasonic; PartNumber: ERJ-L1WKF12CU; TempCo: 100 ppm/C; Value_Code: R100; U/M: EA; Value: 0.1; EIA_Code: E96; SizeX_mm: 6.3; SizeY_mm: 3.2; SizeZ_mm: 0.71; SizeArea_mm2: 20.16; VDC_V: 0V; AEC Category: Q200
R18 = CMP-0022109-5: RES, 1.00 k, 1%, 0.1 W, AEC-Q200 Grade 0, 0603; Manufacturer: Vishay-Dale; CompType: Resistor; Value: 1.00k; Res_ohm: 1k; Value_Code: 1k00; Power_W: 100mW; Value2: 0.1W; VDC_V: 75V; TempCo: 100 ppm/C; SizeArea_mm2: 1.28; SizeX_mm: 1.6; SizeY_mm: 0.8; SizeZ_mm: 1; EIA_Code: E96; AEC Category: Q200; AEC Qualified: Y; AEC Grade: 0
R19 = CMP-0022556-4: RES, 69.8 k, 1%, 0.1 W, AEC-Q200 Grade 0, 0603; PartNumber: CRCW060369K8FKEA; Manufacturer: Vishay-Dale; Value: 69.8k; Value_Code: 69k8; Power_W: 100mW; Value2: 0.1W; VDC_V: 75V; TempCo: 100 ppm/C; SizeArea_mm2: 1.28; SizeX_mm: 1.6; SizeY_mm: 0.8; SizeZ_mm: 1; EIA_Code: E96; AEC Category: Q200; AEC Qualified: Y; AEC Grade: 0
R20 = CMP-0022260-4: RES, 28.0 k, 1%, 0.1 W, AEC-Q200 Grade 0, 0603; Manufacturer: Vishay-Dale; Power_W: 100mW; TempCo: 100 ppm/C; Value_Code: 28k0; Value: 28.0k; EIA_Code: E96; Res_ohm: 28k; SizeX_mm: 1.6; SizeY_mm: 0.8; SizeZ_mm: 1; Value2: 0.1W; SizeArea_mm2: 1.28; AEC Qualified: Y; VDC_V: 75V; AEC Category: Q200; AEC Grade: 0
R21 = CMP-0022252-4: RES, 274 k, 1%, 0.1 W, AEC-Q200 Grade 0, 0603; Manufacturer: Vishay-Dale; Power_W: 100mW; TempCo: 100 ppm/C; Value: 274k; EIA_Code: E96; SizeX_mm: 1.6; SizeY_mm: 0.8; SizeZ_mm: 1; Value2: 0.1W; SizeArea_mm2: 1.28; AEC Qualified: Y; VDC_V: 75V; AEC Category: Q200; AEC Grade: 0
R22 = CMP-0022447-4: RES, 49.9 k, 1%, 0.1 W, AEC-Q200 Grade 0, 0603; Manufacturer: Vishay-Dale; Power_W: 100mW; TempCo: 100 ppm/C; Value_Code: 49k9; Value: 49.9k; EIA_Code: E96; SizeX_mm: 1.6; SizeY_mm: 0.8; SizeZ_mm: 1; Value2: 0.1W; SizeArea_mm2: 1.28; AEC Qualified: Y; VDC_V: 75V; AEC Category: Q200; AEC Grade: 0
R23 = CMP-0021376-3: RES, 63.4, 1%, 0.125 W, AEC-Q200 Grade 0, 0805; PartNumber: CRCW080563R4FKEA; Manufacturer: Vishay-Dale; Value: 63.4; Value_Code: 63R4; Power_W: 125mW; Value2: 0.125W; VDC_V: 150V; TempCo: 100 ppm/C; SizeArea_mm2: 2.5; SizeX_mm: 2; SizeY_mm: 1.25; SizeZ_mm: 1.45; EIA_Code: E96; AEC Category: Q200; AEC Qualified: Y; AEC Grade: 0
R24 R32 R33 = CMP-0021998-4: RES, 10.0 k, 1%, 0.1 W, AEC-Q200 Grade 0, 0603; Manufacturer: Vishay-Dale; CompType: Resistor; Value: 10.0k; Res_ohm: 10k; Value_Code: 10k0; Power_W: 100mW; Value2: 0.1W; VDC_V: 75V; TempCo: 100 ppm/C; SizeArea_mm2: 1.28; SizeX_mm: 1.6; SizeY_mm: 0.8; SizeZ_mm: 1; EIA_Code: E96; AEC Category: Q200; AEC Qualified: Y; AEC Grade: 0
R25 = CMP-0022237-4: RES, 24.9 k, 1%, 0.1 W, AEC-Q200 Grade 0, 0603; PartNumber: CRCW060324K9FKEA; Manufacturer: Vishay-Dale; Value: 24.9k; Value_Code: 24k9; Power_W: 100mW; Value2: 0.1W; VDC_V: 75V; TempCo: 100 ppm/C; SizeArea_mm2: 1.28; SizeX_mm: 1.6; SizeY_mm: 0.8; SizeZ_mm: 1; EIA_Code: E96; AEC Category: Q200; AEC Qualified: Y; AEC Grade: 0
R26 = CMP-0025874-4: RES, 0, 5%, 0.1 W, AEC-Q200 Grade 0, 0603; PartNumber: ERJ-3GEY0R00V; Manufacturer: Panasonic; Value: 0; Value_Code: 0000; Power_W: 100mW; Value2: 0.1W; VDC_V: 50V; TempCo: 600 ppm/C; SizeArea_mm2: 1.28; SizeX_mm: 1.6; SizeY_mm: 0.8; SizeZ_mm: 1; EIA_Code: E24; AEC Category: Q200; AEC Qualified: Y; SizeAreaWB_mm2: 4.68
R27 = CMP-0022126-4: RES, 1.50 k, 1%, 0.1 W, AEC-Q200 Grade 0, 0603; Manufacturer: Vishay-Dale; Power_W: 100mW; TempCo: 100 ppm/C; Value_Code: 1k50; Value: 1.50k; EIA_Code: E96; Res_ohm: 1.5k; SizeX_mm: 1.6; SizeY_mm: 0.8; SizeZ_mm: 1; Value2: 0.1W; SizeArea_mm2: 1.28; AEC Qualified: Y; VDC_V: 75V; AEC Category: Q200; AEC Grade: 0
R28 = CMP-0021998-4: RES, 10.0 k, 1%, 0.1 W, AEC-Q200 Grade 0, 0603; PartNumber: CRCW060310K0FKEA; Manufacturer: Vishay-Dale; Value: 10.0k; Res_ohm: 10k; Value_Code: 10k0; Power_W: 100mW; Value2: 0.1W; VDC_V: 75V; TempCo: 100 ppm/C; SizeArea_mm2: 1.28; SizeX_mm: 1.6; SizeY_mm: 0.8; SizeZ_mm: 1; EIA_Code: E96; AEC Category: Q200; AEC Qualified: Y; AEC Grade: 0
R29 = CMP-0022558-4: RES, 6.04 k, 1%, 0.1 W, AEC-Q200 Grade 0, 0603; Manufacturer: Vishay-Dale; Power_W: 100mW; TempCo: 100 ppm/C; Value_Code: 6k04; Value: 6.04k; EIA_Code: E96; SizeX_mm: 1.6; SizeY_mm: 0.8; SizeZ_mm: 1; Value2: 0.1W; SizeArea_mm2: 1.28; AEC Qualified: Y; VDC_V: 75V; AEC Category: Q200; AEC Grade: 0
R30 = CMP-0022268-4: RES, 2.00 k, 1%, 0.1 W, AEC-Q200 Grade 0, 0603; PartNumber: CRCW06032K00FKEA; Manufacturer: Vishay-Dale; Value: 2.00k; Res_ohm: 2k; Value_Code: 2k00; Power_W: 100mW; Value2: 0.1W; VDC_V: 75V; TempCo: 100 ppm/C; SizeArea_mm2: 1.28; SizeX_mm: 1.6; SizeY_mm: 0.8; SizeZ_mm: 1; EIA_Code: E96; AEC Category: Q200; AEC Qualified: Y; AEC Grade: 0
R31 = CMP-0022458-4: RES, 4.99 k, 1%, 0.1 W, AEC-Q200 Grade 0, 0603; Manufacturer: Vishay-Dale; Power_W: 100mW; TempCo: 100 ppm/C; Value_Code: 4k99; Value: 4.99k; EIA_Code: E96; SizeX_mm: 1.6; SizeY_mm: 0.8; SizeZ_mm: 1; Value2: 0.1W; SizeArea_mm2: 1.28; AEC Qualified: Y; VDC_V: 75V; AEC Category: Q200; AEC Grade: 0
R34 = CMP-0022115-4: RES, 1.15 k, 1%, 0.1 W, AEC-Q200 Grade 0, 0603; Manufacturer: Vishay-Dale; Power_W: 100mW; TempCo: 100 ppm/C; Value_Code: 1k15; Value: 1.15k; EIA_Code: E96; SizeX_mm: 1.6; SizeY_mm: 0.8; SizeZ_mm: 1; Value2: 0.1W; SizeArea_mm2: 1.28; AEC Qualified: Y; VDC_V: 75V; AEC Category: Q200; AEC Grade: 0
T2 = CMP-0087126-1: Transformer, SMT Flyback for PoE/PD, 25W, 24V, 1A; Manufacturer: Wurth; SizeZ_mm: 11.43mm; DCR_ohm: 0.308; Rsec1_ohm: 0.249; Ind_H: 80µH; Ns1toNp: 1:0.187:0.187; AEC Qualified: No
U1 = CMP-0031315-4: IEEE 802.3at, High Efficiency, PoE Interface and DC/DC Controller, PWP0020D (HTSSOP-20); Manufacturer: Texas Instruments; PoE Inrush Limit(Typ)(mA): 140; Rating: Catalog; PoE I/F & DC DC Control: TRUE; SizeY_mm: 6.5; SizeAreaWB_mm2: 71.4; AEC Qualified: N; Duty Cycle(%): 78; Switching Frequency: Synchronizable and Programmable; AEC Category: Q200; SizeZ_mm: 1.2; PoE Standards Supported: 802.3at type1, 2; PoE Current Limit(Min)(mA): 850; Eco-Plan: Green (RoHS & no Sb/Br); Driven/Active Clamp (Second Gate Drive): Yes; CompType: IC; Auxiliary Power Rails Supported: 24V-57V; Auxiliary/Local Power Support: Programmable; SizeX_mm: 6.4; rDS(on) per FET(Typ)(mOhms): 430; Fault Response: Auto Retry; PD Power Level: 25W; UVLO: Unified; SizeArea_mm2: 41.6
U2 = CMP-0006167-3: Optocoupler, 3.75 kV, 300-600% CTR, SMT; Manufacturer: Sharp Microelectronics; CTR (Max): 600%; SizeAreaWB_mm2: 4; CTR (Min): 300%; SizeZ_mm: 1; Voltage_Isolation_Vrms: 3.75kV
U3 = CMP-0006166-3: Optocoupler, 3.75 kV, 80-160% CTR, SMT; Manufacturer: Vishay-Semiconductor; CTR (Max): 160%; SizeAreaWB_mm2: 43.65; CTR (Min): 80%; SizeZ_mm: 2.3; SizeX_mm: 7; SizeY_mm: 2.85; SizeArea_mm2: 19.95; Voltage_Isolation_Vrms: 3.75kV
U4 = CMP-0084729-1: Programmable Shunt Regulator with Optimized Reference Current, DBZ0003A (SOT-23-3); Manufacturer: Texas Instruments; SizeY_mm: 3; SizeZ_mm: 1.12; SizeX_mm: 2.5; SizeAreaWB_mm2: 14; CompType: IC; AEC Qualified: N; AEC Category: Q200; SizeArea_mm2: 7.5

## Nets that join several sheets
PGND: PMP22301_RevB_SH1 (C7.1 L3.1), PMP22301_RevB_SH2 (19 pins)
AUX: PMP22301_RevB_SH1 (C7.2 D1.2 L2.1), PMP22301_RevB_SH2 (R16.2)
VDD: PMP22301_RevB_SH1 (C10.1 D1.1 L1.2), PMP22301_RevB_SH2 (9 pins)
VSS: PMP22301_RevB_SH1 (C10.2 L4.2), PMP22301_RevB_SH2 (5 pins)

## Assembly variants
001: not fitted L6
